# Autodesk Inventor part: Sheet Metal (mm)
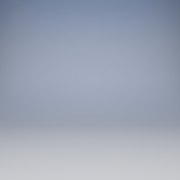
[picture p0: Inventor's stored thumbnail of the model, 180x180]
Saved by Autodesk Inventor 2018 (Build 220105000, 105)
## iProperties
Created: 2017-02
Part Number: Sheet Metal (mm)
Material: Ogólny
Document SubType Name: Konstrukcja blachowa
Density: 1 g/cm^3
Appearance: Domyślna
Sheet Metal Rule: Domyślny_mm
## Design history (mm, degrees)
other parameters: "Grubość" = 0.5 (derived), "WspółczynnikK" = 4.4, "PromieńGięcia" = 0.5 (= Grubość), "SzerokośćGięciaPodcięcia" = 0.5 (= Grubość), "GłębokośćGięciaPodcięcia" = 0.25 (= 0.5 x Grubość), "RozmiarPodcięciaNarożnika" = 2 (= 4 x Grubość), "OdstępPołączenia" = 0.01, "MinimalnaPozostałość" = 1 (= 2 x Grubość), "PromieńPrzejścia" = 0.5 (= PromieńGięcia), "Rozmiar_promienia_Jacobiego" = 0.5 (= PromieńGięcia), "Wielk_odstępu" = 0.5 (= Grubość)
